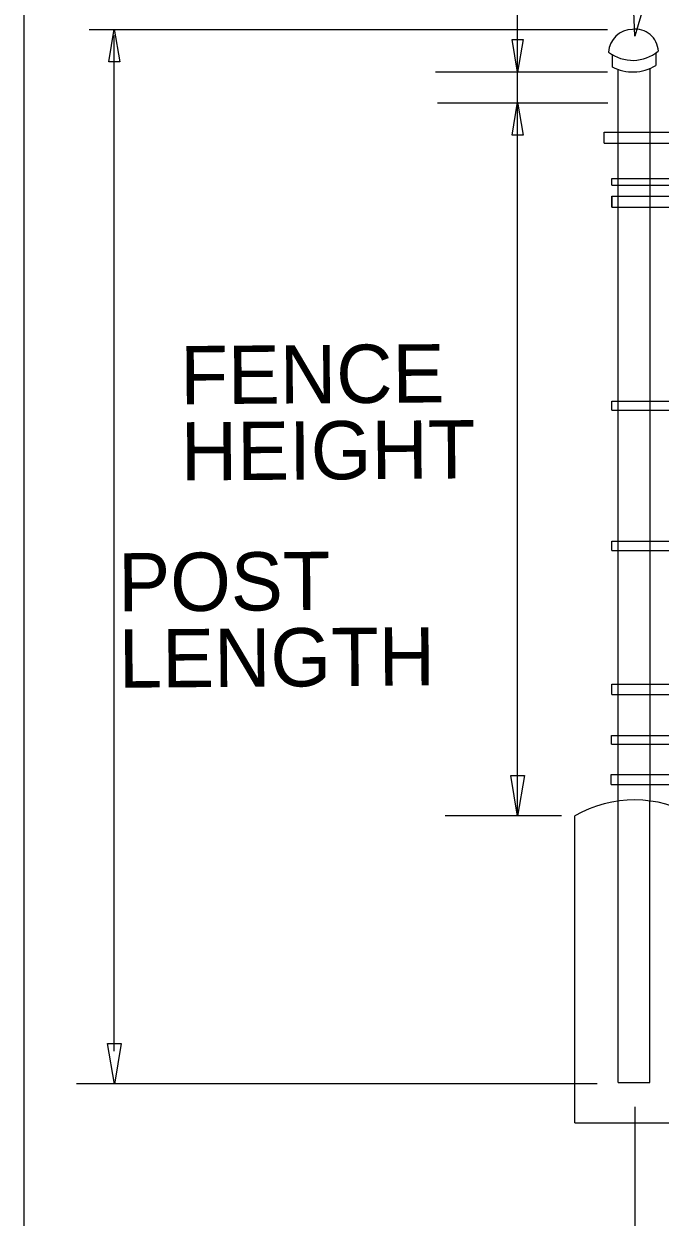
# Model space of a CAD drawing. Extents: x 0 to 1270, y 0 to 830.
# Drawn here: x 0 to 53.5, y 344.3 to 444.7 of the extents above; entities that cross this region are included whole.
import ezdxf

# ---------------------------------------------------------------- set-up
doc = ezdxf.new("R2010")
doc.units = 0
for name, color, linetype in [('CT_Border_Perimeter_Shape', 7, 'Continuous'), ('CT_Dimensions', 7, 'Continuous'), ('CT_Title_Block_Text', 7, 'Continuous'), ('sb_Existing Concrete', 7, 'Continuous'), ('sb_Existing Structural Steel', 7, 'Continuous')]:
    doc.layers.add(name, color=color, linetype=linetype)

# ---------------------------------------------------------------- blocks, each defined once
blk = doc.blocks.new('BDR_CTDOT_Standards')
at = {"layer": 'CT_Border_Perimeter_Shape'}
blk.add_lwpolyline([(0, 0), (1270, 0), (1270, 830), (0, 830)], close=True, dxfattribs=at)

msp = doc.modelspace()

# ---------------------------------------------------------------- linework, layer by layer
at = {"layer": 'CT_Dimensions'}
for p, q in [((41.52, 438.04), (41.5, 449.15)), ((5.48, 444.21), (49.08, 444.21)), ((7.58, 358.26), (7.58, 443.7)), ((34.62, 440.65), (49.06, 440.65)), ((34.77, 438.05), (49.09, 438.05)), ((41.52, 378.1), (41.52, 438.04)), ((35.41, 378.1), (45.21, 378.1)), ((4.42, 355.55), (48.21, 355.55)), ((51.36, 353.58), (51.36, 328.02))]:
    msp.add_line(p, q, dxfattribs=at)
for points in [[(52.16, 446.31), (51.38, 443.64), (51.25, 446.42)], [(7.14, 441.48), (7.6, 444.22), (8.06, 441.48)], [(41.97, 443.37), (41.51, 440.62), (41.06, 443.37)], [(41.06, 435.33), (41.51, 438.08), (41.97, 435.33)], [(42.09, 381.47), (41.52, 378.05), (40.95, 381.47)], [(8.18, 358.93), (7.61, 355.5), (7.04, 358.93)]]:
    msp.add_lwpolyline(points, close=True, dxfattribs=at)
at = {"layer": 'sb_Existing Concrete'}
for q in [(46.32, 378.06), (56.43, 352.25)]:
    msp.add_line((46.33, 352.25), q, dxfattribs=at)
msp.add_arc((51.35, 369.25), 10.15, 59.953, 119.6876, dxfattribs=at)
at = {"layer": 'sb_Existing Structural Steel'}
for p, q in [((49.46, 442.1), (49.47, 441.05)), ((53.13, 442.22), (53.14, 441.17)), ((49.97, 379.36), (49.97, 440.86)), ((52.65, 379.3), (52.65, 440.88)), ((48.79, 435.58), (54.27, 435.58)), ((48.79, 434.65), (54.27, 434.65)), ((48.8, 434.64), (48.8, 435.57)), ((49.45, 431.67), (56.15, 431.67)), ((49.45, 431.11), (49.45, 431.67)), ((49.45, 431.11), (56.15, 431.11)), ((49.45, 430.19), (56.15, 430.19)), ((49.45, 429.27), (49.45, 430.19)), ((49.45, 430.19), (49.45, 429.27)), ((49.45, 429.27), (56.15, 429.27)), ((49.45, 412.19), (49.45, 412.94)), ((49.45, 412.94), (55.18, 412.94)), ((49.45, 412.19), (55.19, 412.19)), ((49.45, 400.37), (49.45, 401.18)), ((49.45, 401.18), (55.18, 401.18)), ((49.45, 400.37), (55.2, 400.37)), ((49.45, 388.28), (49.45, 389.13)), ((49.45, 389.13), (55.19, 389.13)), ((49.45, 388.28), (55.17, 388.28)), ((49.41, 384.83), (56.11, 384.83)), ((49.41, 384.1), (49.41, 384.83)), ((49.41, 384.1), (56.11, 384.1)), ((49.39, 381.54), (56.1, 381.54)), ((49.39, 380.7), (49.39, 381.54)), ((49.39, 380.7), (56.1, 380.7)), ((49.97, 355.65), (49.97, 379.31)), ((52.64, 355.65), (52.64, 379.31)), ((49.97, 355.65), (52.64, 355.65))]:
    msp.add_line(p, q, dxfattribs=at)
for centre, radius, start, end in [((51.16, 442.22), 1.99, 89.8895, 177.7676), ((51.42, 442.3), 1.93, 2.5633, 97.4829), ((51.2, 444.95), 3.34, 232.557, 309.8979), ((51.2, 444.35), 3.72, 242.2669, 301.3455)]:
    msp.add_arc(centre, radius, start, end, dxfattribs=at)

# ---------------------------------------------------------------- block references
at = {"layer": 'CT_Title_Block_Text'}
msp.add_blockref('BDR_CTDOT_Standards', (0, 0), dxfattribs=at)

# ---------------------------------------------------------------- texts
at = {"layer": 'CT_Dimensions'}
for s, p in [('FENCE ', (13.17, 412.68)), ('HEIGHT', (13.22, 406.27)), ('POST', (7.95, 395.25)), ('LENGTH', (8, 388.84))]:
    msp.add_text(s, height=4.901, rotation=0.4256, dxfattribs=at).set_placement(p)

doc.saveas('drawing.dxf')
